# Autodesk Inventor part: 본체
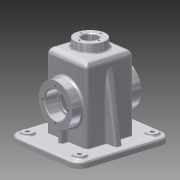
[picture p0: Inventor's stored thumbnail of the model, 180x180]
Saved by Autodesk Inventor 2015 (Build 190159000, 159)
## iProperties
Created: 2016-02
Part Number: 본체
Material: 알루미늄 6061
Document SubType Name: Modeling
Designer: Administrator
Density: 2.7 g/cm^3
Appearance: 알루미늄 - 평지
Mass: 799.07 g
Surface Area: 912.514 cm^2
Volume: 295.952 cm^3
Author: Administrator
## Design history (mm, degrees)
sketch "스케치1"
  geometry: L1 (-57.5, -65)-(57.5, -65); L2 (57.5, -65)-(57.5, 65); L3 (57.5, 65)-(-57.5, 65); L4 (-57.5, 65)-(-57.5, -65); L5 (-57.5, -65)-(57.5, 65); L6 (57.5, -65)-(-57.5, 65); 1 further point
  constraints: 12 end point, 2 midpoint, 2 parallel, 1 horizontal, 1 perpendicular
  dimensions: "d0" = 130 distance of L1.end L2.end; "d1" = 115 distance of L1.start L1.end
extrude "돌출1" new body sketch "스케치1" distance "d2" = 8; taper "d3" = 0 deg
sketch "스케치2"
  geometry: L1 (32.5, 32.5)-(-32.5, 32.5); L2 (-32.5, 32.5)-(-32.5, -32.5); L3 (-32.5, -32.5)-(32.5, -32.5); L4 (32.5, -32.5)-(32.5, 32.5); L5 (32.5, 32.5)-(-32.5, -32.5); L6 (-32.5, 32.5)-(32.5, -32.5); 1 further point
  constraints: 12 end point, 2 midpoint, 2 parallel, 1 horizontal, 1 perpendicular
  dimensions: "d4" = 65 distance of L1.end L2.end; "d5" = 65 distance of L1.start L1.end
extrude "돌출2" join sketch "스케치2" distance "d6" = 98; taper "d7" = 0 deg
sketch "스케치3"
  geometry: L1 (-52.5, -60)-(52.5, -60); L2 (52.5, -60)-(52.5, 60); L3 (52.5, 60)-(-52.5, 60); L4 (-52.5, 60)-(-52.5, -60); L5 (-52.5, -60)-(52.5, 60); L6 (52.5, -60)-(-52.5, 60); 1 further point
  constraints: 12 end point, 2 midpoint, 2 parallel, 1 horizontal, 1 perpendicular
  dimensions: "d8" = 120 distance of L1.end L2.end; "d9" = 105 distance of L1.start L1.end
extrude "돌출3" join sketch "스케치3" distance "d10" = 2; taper "d11" = 0 deg
sketch "스케치4"
  geometry: L1 (-20, -10)-(85, -10) reference; C1 r 27.5 at (32.5, 45); 1 further point
  constraints: 1 centre point, 1 vertical alignment
  dimensions: "d12" = 55 distance from line of L1 C1.centre; "d13" = 55 diameter of C1
extrude "돌출4" join sketch "스케치4" distance "d14" = 15; taper "d15" = 0 deg
sketch "스케치5"
  geometry: L1 (-20, -10)-(85, -10) reference; C1 r 27.5 at (32.5, 45); 1 further point
  constraints: 1 centre point, 1 vertical alignment
  dimensions: "d16" = 55 diameter of C1; "d17" = 55 distance from line of L1 C1.centre
extrude "돌출5" join sketch "스케치5" distance "d18" = 15; taper "d19" = 0 deg
sketch "스케치6"
  geometry: L1 (3, 42.5)-(-3, 42.5); L2 (-3, 42.5)-(-3, -42.5); L3 (-3, -42.5)-(3, -42.5); L4 (3, -42.5)-(3, 42.5); L5 (3, 42.5)-(-3, -42.5); L6 (-3, 42.5)-(3, -42.5); 1 further point
  constraints: 12 end point, 2 midpoint, 2 parallel, 1 horizontal, 1 perpendicular
  dimensions: "d20" = 6 distance of L1.start L1.end; "d21" = 85 distance of L1.end L2.end
extrude "돌출6" join sketch "스케치6" distance "d22" = 25; taper "d23" = 0 deg
sketch "스케치8"
  geometry: L1 (-32.5, 8)-(-32.5, 106) reference; L2 (32.5, 8)-(32.5, 106) reference; L3 (-47.5, 8)-(-32.5, 93.069); L4 (32.5, 93.069)-(47.5, 8); L5 (57.5, 8)-(-57.5, 8) reference; L6 (-47.5, 8)-(47.5, 8); L7 (-32.5, 93.069)-(32.5, 93.069); 1 further point
  constraints: 8 end point, 3 point on line, 2 horizontal
  dimensions: "d28" = 10 distance of L3.start L5.end; "d29" = 10 distance of L5.start L4.end; "d30" = 80 deg angle of L5 L4
extrude "돌출7" join sketch "스케치8" stored distance "d31" = 10; taper "d32" = 0 deg
sketch "스케치10"
  geometry: L1 (-27.5, -27.5)-(27.5, -27.5); L2 (27.5, -27.5)-(27.5, 27.5); L3 (27.5, 27.5)-(-27.5, 27.5); L4 (-27.5, 27.5)-(-27.5, -27.5); L5 (-27.5, -27.5)-(27.5, 27.5); L6 (27.5, -27.5)-(-27.5, 27.5); 1 further point
  constraints: 12 end point, 2 midpoint, 2 parallel, 1 horizontal, 1 perpendicular
  dimensions: "d36" = 55 distance of L1.end L2.end; "d37" = 55 distance of L1.start L1.end
extrude "돌출9" cut sketch "스케치10" distance "d38" = 105; taper "d39" = 0 deg
sketch "스케치11"
  geometry: L1 (52.5, -53)-(-52.5, -53) reference; C1 r 17.5 at (0, 0); 1 further point
  constraints: 1 centre point, 1 vertical alignment
  dimensions: "d40" = 35 diameter of C1; "d41" = 53 distance from line of L1 C1.centre
extrude "돌출10" cut sketch "스케치11" distance "d42" = 17; taper "d43" = 0 deg
sketch "스케치12"
  geometry: L1 (-27.5, -55)-(27.5, -55) reference; C1 r 17.5 at (0, 0); 1 further point
  constraints: 1 centre point, 1 vertical alignment
  dimensions: "d44" = 35 diameter of C1; "d45" = 55 distance from line of L1 C1.centre
extrude "돌출11" cut sketch "스케치12" distance "d46" = 17; taper "d47" = 0 deg
sketch "스케치13"
  geometry: L1 (-27.5, -55)-(27.5, -55) reference; L2 (52.5, -53)-(-52.5, -53) reference; C1 r 15 at (0, 0); 2 further points
  constraints: 1 centre point, 1 midpoint, 1 vertical alignment
  dimensions: "d48" = 55 distance from line of L1 C1.centre; "d49" = 30 diameter of C1
extrude "돌출12" cut sketch "스케치13" stored distance "d50" = 17; taper "d51" = 0 deg
node "작업 평면4"
sketch "스케치16"
  geometry: C1 r 20 at (0, 0); 1 further point
  constraints: 1 centre point, 1 coincident
  dimensions: "d58" = 40 diameter of C1
extrude "돌출14" join sketch "스케치16" stored distance "d59" = 17; taper "d60" = 5 deg
sketch "스케치17"
  geometry: C1 r 10.5 at (0, 0); 1 further point
  constraints: 1 centre point, 1 coincident
  dimensions: "d61" = 21 diameter of C1
extrude "돌출15" cut sketch "스케치17" stored distance "d62" = 17; taper "d63" = 0 deg
sketch "스케치18"
  geometry: L1 (52.5, -55)-(-52.5, -55) reference; 2 further points
  constraints: 1 vertical alignment
  dimensions: "d64" = 76 distance from line of L1 point (0, 21)
hole "구멍1" sketch "스케치18" at (0, 21) diameter "d65" = 3.242; stored, may be unused: countersink angle "d69" = 90 deg, drill point angle "d71" = 118 deg; dims "d66" = 8, "d67" = 4, "d68" = 2, "d70" = 10
sketch "스케치19"
  geometry: C1 r 1.621 at (0, 21) reference; 2 further points
  constraints: 1 coincident
hole "구멍2" sketch "스케치19" at (0, 21) diameter "d75" = 3.242; stored, may be unused: countersink angle "d79" = 90 deg, drill point angle "d81" = 118 deg; dims "d76" = 8, "d77" = 4, "d78" = 2, "d80" = 10
sketch "스케치20"
  geometry: 2 further points
  constraints: 1 horizontal alignment
  dimensions: "d85" = 14.5 distance of point (-14.5, 0) point (0, 0)
hole "구멍3" sketch "스케치20" at (-14.5, 0) diameter "d86" = 2.459; stored, may be unused: countersink angle "d90" = 90 deg, drill point angle "d92" = 118 deg; dims "d87" = 7, "d88" = 4, "d89" = 2, "d91" = 9
sketch "스케치22"
  geometry: L1 (-57.5, 65)-(-57.5, -65) reference; L2 (-57.5, -65)-(57.5, -65) reference; C1 r 7.5 at (-42.5, -50); C2 r 7.5 at (-42.5, 50); C3 r 7.5 at (42.5, -50); C4 r 7.5 at (42.5, 50); 1 further point
  constraints: 4 centre point, 1 horizontal, 1 vertical, 6 other
  dimensions: "d109" = 15 distance from line of L1 C1.centre; "d110" = 15 distance from line of L2 C1.centre; "d111" = 15 diameter of C1; "d114" = 100 distance of C1.centre C2.centre; "d117" = 85 distance of C1.centre C3.centre
extrude "돌출17" join sketch "스케치22" distance "d120" = 3; taper "d121" = 0 deg
sketch "스케치23"
  geometry: L1 (52.5, 60)-(-52.5, 60) reference; L2 (-52.5, 60)-(-52.5, -60) reference; C1 r 3 at (-42.5, 50); C2 r 3 at (42.5, 50); C3 r 3 at (-42.5, -50); C4 r 3 at (42.5, -50); 1 further point
  constraints: 4 centre point, 1 horizontal, 1 vertical, 6 other
  dimensions: "d122" = 10 distance from line of L1 C1.centre; "d123" = 10 distance from line of L2 C1.centre; "d124" = 6 diameter of C1; "d127" = 85 distance of C1.centre C2.centre; "d130" = 100 distance of C1.centre C3.centre
extrude "돌출18" cut sketch "스케치23" stored distance "d133" = 3; taper "d134" = 0 deg
fillet "모깎기1" dims "d135" = 4
fillet "모깎기2" dims "d136" = 15
fillet "모깎기3" dims "d137" = 0.3
fillet "모깎기4" dims "d138" = 10
fillet "모깎기5" dims "d139" = 3
fillet "모깎기9" dims "d143" = 3
fillet "모깎기10" dims "d144" = 3
fillet "모깎기11" dims "d145" = 3
fillet "모깎기12" dims "d146" = 3
fillet "모깎기13" dims "d147" = 8
fillet "모깎기14" dims "d148" = 3
fillet "모깎기15" dims "d149" = 3
fillet "모깎기16" dims "d150" = 3
fillet "모깎기17" dims "d151" = 1
chamfer "모따기1" distance "d152" = 1; stored, may be unused: second distance "d153" = 2, angle "d154" = 45 deg
fillet "모깎기18" dims "d155" = 3
fillet "모깎기19" dims "d156" = 3
node "작업 평면5"
sketch "스케치24"
  geometry: L1 (-20, 118)-(20, 118) reference; L2 (32.5, 9)-(32.5, 98) reference; 2 further points
  constraints: 1 other
  dimensions: "d158" = 26 distance from line of point (0, 92) L1; "d159" = 32.5 distance from line of L2 point (0, 92)
feature "엠보싱1" sketch "스케치24" dims "d8" = 120, "d9" = 105, "d160" = 0.5, "d161" = 0
fillet "모깎기20" dims "d162" = 3
node "솔리드1"
pattern_circular "원형 패턴1" dims angle "d73" = 360 deg
pattern_circular "원형 패턴2" dims angle "d83" = 360 deg
pattern_circular "원형 패턴3" dims angle "d94" = 360 deg
other parameters: "d57" = 118, "d157" = -35
